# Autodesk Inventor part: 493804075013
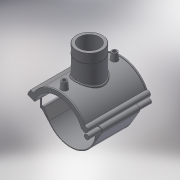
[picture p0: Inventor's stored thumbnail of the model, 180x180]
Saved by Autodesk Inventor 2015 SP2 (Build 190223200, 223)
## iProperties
Created: 2017-07
Part Number: 493804075013
Material: Generic
Description: PLASSON TRANSITION SADDLE 75-1.1/4"
Document SubType Name: Modeling
Designer: KIM
Density: 1 g/cm^3
Appearance: Default
Author: KIM
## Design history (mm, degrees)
derived "493804.ipt"
feature "Solid1::493804.ipt"
tag "TaggingFeature1"
body "Solid1"
other parameters: "d_" = 75, "B_" = 117, "H_" = 53, "L_" = 118, "d_t" = 6, "G_" = 38.952, "d148" = 1.125, "d160" = 1.125, "d169" = 2.1, "d192" = 4.2, "d0" = 75, "d1" = 97.5, "d2" = 117, "d3" = 18.75, "d4" = 118, "d5" = 0, "d6" = 0.1, "d8" = 0, "d19" = 6, "d20" = 6, "d21" = 70.8, "d23" = 0, "d24" = 35.4, "d26" = 0, "d27" = 3, "d28" = 3, "d29" = 3, "d30" = 25, "d31" = 6, "d32" = 0, "d33" = 0, "d34" = 0.6, "d40" = 50.7, "d41" = 54.5328, "d43" = 0, "d45" = 0, "d47" = 101.75, "d48" = 50.6376, "d50" = 0, "d70" = 15, "d72" = 0, "d73" = 6, "d75" = 5, "d76" = 0, "d77" = 3.75, "d78" = 67.5, "d79" = 15, "d80" = 47.2, "d82" = 5 deg, "d84" = 4, "d85" = 14, "d86" = 0, "d87" = 3, "d88" = 0, "d89" = 1, "d90" = 1, "d91" = 94.4, "d92" = 0, "d93" = 0.5, "d94" = 39.47368, "d96" = 99.45, "d97" = 2.36, "d98" = 0, "d102" = 1.16856, "d103" = 38.952, "d104" = 31.8, "d105" = 0, "d106" = 31.1616, "d108" = 0, "d109" = -17.66667, "d111" = 0.5, "d112" = 0.5, "d113" = 0, "d114" = 0.5, "d117" = 0.38952, "d120" = 140 deg, "d121" = 24.228, "d122" = 20 deg, "d123" = 195, "d124" = 58.5, "d126" = 0, "d143" = 77.25, "d145" = 17.30769, "d149" = 1.125, "d150" = 19.03846, "d153" = 118, "d154" = 0, "d156" = 48.75, "d157" = 160 deg, "d159" = 4.5, "d161" = 1.125, "d162" = 70.8, "d163" = 0, "d164" = 37.5, "d167" = 7.5, "d168" = 47.56098, "d170" = 2.1, "d172" = 0, "d173" = 1, "d175" = 37.5, "d176" = 20 deg, "d177" = 5.25, "d178" = 22.5, "d180" = 0, "d183" = 9, "d184" = 4.2, "d185" = 38.35, "d186" = 38.35, "d187" = 48.75, "d188" = 6.75, "d189" = 5.25, "d190" = 0, "d191" = 58.5, "d193" = 4.2, "d194" = 2.95, "d195" = 90 deg, "d197" = 0, "d199" = 0
